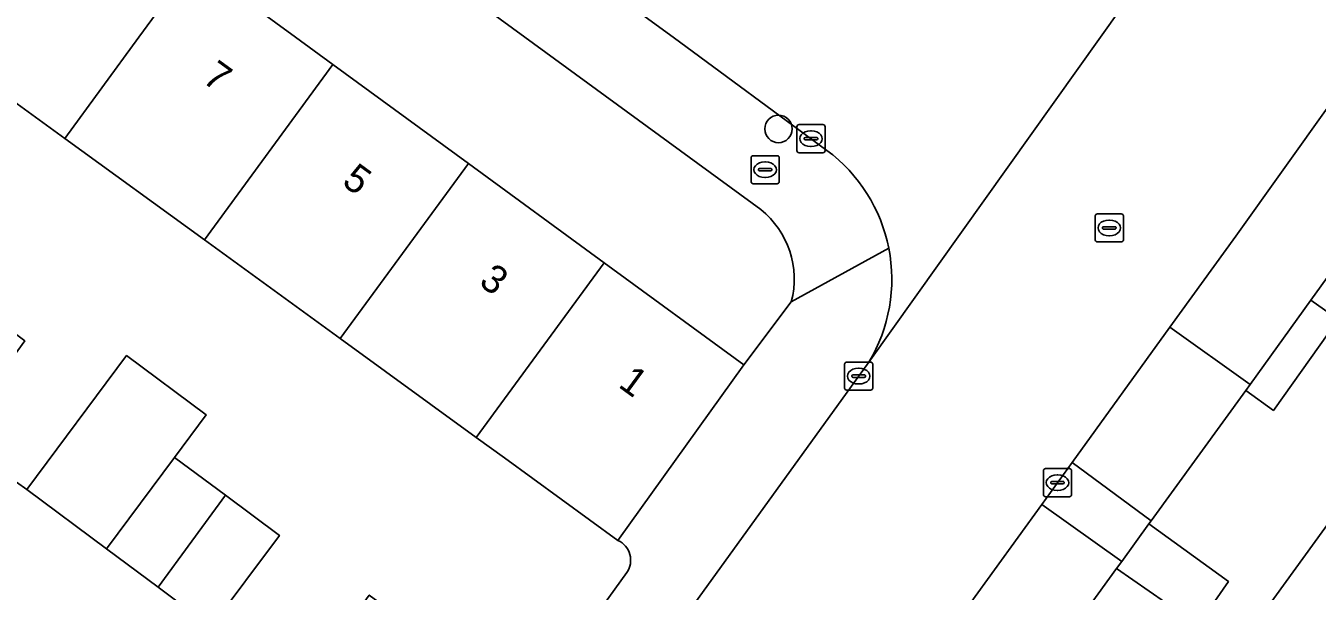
# Model space of a CAD drawing. Extents: x 159674 to 160531, y 382172 to 382904.
# Drawn here: x 160175.73 to 160221.75, y 382480.25 to 382500.4 of the extents above; entities that cross this region are included whole.
import ezdxf

# ---------------------------------------------------------------- set-up
doc = ezdxf.new("R2010")
doc.units = 0
for name, color, linetype in [('IMGEO_Boom', 7, 'Continuous'), ('IMGEO_Brandkraan', 7, 'Continuous'), ('IMGEO_Erf', 7, 'Continuous'), ('IMGEO_Groenvoorziening', 7, 'Continuous'), ('IMGEO_Kolk', 7, 'Continuous'), ('IMGEO_Pand', 7, 'Continuous'), ('IMGEO_Pand_nummerreeks', 7, 'Continuous'), ('IMGEO_Rijbaan_lokaal_gesloten', 7, 'Continuous'), ('IMGEO_Rijbaan_lokaal_open', 7, 'Continuous'), ('IMGEO_Rioolput', 7, 'Continuous'), ('IMGEO_Voetpad_open', 7, 'Continuous')]:
    doc.layers.add(name, color=color, linetype=linetype)

msp = doc.modelspace()

# ---------------------------------------------------------------- linework, layer by layer
at = {"layer": 'IMGEO_Boom'}
msp.add_circle((160202.556, 382496.725), 0.489, dxfattribs=at)
at = {"layer": 'IMGEO_Brandkraan'}
for p, q in [((160201.579, 382494.846), (160201.579, 382495.698)), ((160201.654, 382495.772), (160202.506, 382495.772)), ((160202.58, 382495.698), (160202.58, 382494.846)), ((160201.838, 382495.266), (160201.838, 382495.278)), ((160201.881, 382495.315), (160202.279, 382495.315)), ((160202.067, 382495.552), (160202.092, 382495.552)), ((160202.322, 382495.278), (160202.322, 382495.266)), ((160202.506, 382494.772), (160201.654, 382494.772)), ((160202.276, 382495.229), (160201.878, 382495.229)), ((160202.09, 382494.992), (160202.065, 382494.992))]:
    msp.add_line(p, q, dxfattribs=at)
for points in [[(160201.579, 382494.846), (160201.579, 382495.698)], [(160201.654, 382495.772), (160202.506, 382495.772)], [(160202.58, 382495.698), (160202.58, 382494.846)], [(160202.506, 382494.772), (160201.654, 382494.772)]]:
    msp.add_lwpolyline(points, dxfattribs=at)
for centre, radius, start, end in [((160201.656, 382495.696), 0.0765, 91.552, 178.448), ((160201.656, 382495.696), 0.0765, 91.552, 178.448), ((160202.504, 382495.696), 0.0765, 1.552, 88.448), ((160202.504, 382495.696), 0.0765, 1.552, 88.448), ((160201.878, 382495.275), 0.0403, 85.8775, 175.7526), ((160201.875, 382495.265), 0.0366, 178.938, 274.7102), ((160202.279, 382495.272), 0.043, 264.8664, 352.4533), ((160202.283, 382495.277), 0.0386, 1.7309, 96.639), ((160201.656, 382494.848), 0.0765, 181.552, 268.448), ((160201.656, 382494.848), 0.0765, 181.552, 268.448), ((160202.504, 382494.848), 0.0765, 271.552, 358.448), ((160202.504, 382494.848), 0.0765, 271.552, 358.448)]:
    msp.add_arc(centre, radius, start, end, dxfattribs=at)
for centre, major_axis, ratio, start_param, end_param in [((160202.066, 382495.272), (-0.387, 0.002), 0.722429, 4.712389, 7.853982), ((160202.091, 382495.272), (-0.39, 0.002), 0.717154, 1.570796, 4.712389)]:
    msp.add_ellipse(centre, major_axis=major_axis, ratio=ratio, start_param=start_param, end_param=end_param, dxfattribs=at)
at = {"layer": 'IMGEO_Erf'}
for points in [[(160193.511, 382500), (160179.581, 382510.186), (160176.698, 382506.323), (160181.704, 382502.662), (160185.344, 382500), (160186.672, 382499.029), (160191.502, 382495.496), (160196.341, 382491.958), (160201.314, 382488.321), (160203.011, 382490.565)], [(160182.094, 382492.77), (160177.116, 382496.389), (160172.149, 382500), (160165.851, 382491.086), (160168.791, 382488.896), (160171.386, 382492.38), (160173.197, 382491.031), (160175.695, 382489.17), (160173.177, 382485.697), (160175.768, 382483.874), (160179.323, 382488.647), (160182.164, 382486.531), (160181.035, 382485.016), (160182.848, 382483.665), (160184.767, 382482.236), (160182.34, 382478.979), (160182.963, 382478.515), (160185.543, 382476.768), (160187.968, 382480.105), (160192.854, 382476.554), (160193.609, 382475.995), (160197.153, 382480.914)], [(160201.923, 382493.849), (160193.511, 382500)], [(160196.833, 382482.055), (160192.788, 382484.995), (160191.782, 382485.726), (160186.934, 382489.251), (160182.094, 382492.77)]]:
    msp.add_lwpolyline(points, dxfattribs=at)
for centre, radius, start, end in [((160199.942, 382491.37), 3.173, 345.2972, 51.3632), ((160196.512, 382481.349), 0.775, 325.8286, 65.5044)]:
    msp.add_arc(centre, radius, start, end, dxfattribs=at)
at = {"layer": 'IMGEO_Groenvoorziening'}
for points in [[(160222.498, 382489.927), (160221.527, 382490.625), (160219.36, 382487.613), (160219.207, 382487.402), (160220.191, 382486.689)], [(160215.757, 382482.642), (160214.787, 382481.302), (160214.604, 382481.05), (160217.516, 382479.035), (160218.591, 382480.589)]]:
    msp.add_lwpolyline(points, close=True, dxfattribs=at)
at = {"layer": 'IMGEO_Kolk'}
for p, q in [((160203.212, 382495.953), (160203.212, 382496.805)), ((160203.287, 382496.879), (160204.139, 382496.879)), ((160203.7, 382496.659), (160203.725, 382496.659)), ((160204.213, 382496.805), (160204.213, 382495.953)), ((160203.471, 382496.373), (160203.471, 382496.385)), ((160203.909, 382496.336), (160203.511, 382496.336)), ((160203.514, 382496.422), (160203.912, 382496.422)), ((160203.955, 382496.385), (160203.955, 382496.373)), ((160204.139, 382495.879), (160203.287, 382495.879)), ((160203.723, 382496.099), (160203.698, 382496.099)), ((160204.912, 382487.487), (160204.912, 382488.339)), ((160204.987, 382488.413), (160205.839, 382488.413)), ((160205.913, 382488.339), (160205.913, 382487.487)), ((160205.171, 382487.907), (160205.171, 382487.919)), ((160205.609, 382487.87), (160205.211, 382487.87)), ((160205.214, 382487.956), (160205.612, 382487.956)), ((160205.4, 382488.193), (160205.425, 382488.193)), ((160205.655, 382487.919), (160205.655, 382487.907)), ((160205.839, 382487.413), (160204.987, 382487.413)), ((160205.423, 382487.633), (160205.398, 382487.633)), ((160211.996, 382483.689), (160211.996, 382484.541)), ((160212.071, 382484.615), (160212.923, 382484.615)), ((160212.484, 382484.395), (160212.509, 382484.395)), ((160212.997, 382484.541), (160212.997, 382483.689)), ((160212.255, 382484.109), (160212.255, 382484.121)), ((160212.693, 382484.072), (160212.295, 382484.072)), ((160212.298, 382484.158), (160212.696, 382484.158)), ((160212.507, 382483.835), (160212.482, 382483.835)), ((160212.739, 382484.121), (160212.739, 382484.109)), ((160212.923, 382483.615), (160212.071, 382483.615))]:
    msp.add_line(p, q, dxfattribs=at)
for points in [[(160203.212, 382495.953), (160203.212, 382496.805)], [(160203.287, 382496.879), (160204.139, 382496.879)], [(160204.213, 382496.805), (160204.213, 382495.953)], [(160204.139, 382495.879), (160203.287, 382495.879)], [(160204.912, 382487.487), (160204.912, 382488.339)], [(160204.987, 382488.413), (160205.839, 382488.413)], [(160205.913, 382488.339), (160205.913, 382487.487)], [(160205.839, 382487.413), (160204.987, 382487.413)], [(160211.996, 382483.689), (160211.996, 382484.541)], [(160212.071, 382484.615), (160212.923, 382484.615)], [(160212.997, 382484.541), (160212.997, 382483.689)], [(160212.923, 382483.615), (160212.071, 382483.615)]]:
    msp.add_lwpolyline(points, dxfattribs=at)
for centre, radius, start, end in [((160203.289, 382496.803), 0.0765, 91.552, 178.448), ((160203.289, 382496.803), 0.0765, 91.552, 178.448), ((160204.137, 382496.803), 0.0765, 1.552, 88.448), ((160204.137, 382496.803), 0.0765, 1.552, 88.448), ((160203.511, 382496.382), 0.0403, 85.8775, 175.7526), ((160203.508, 382496.372), 0.0366, 178.938, 274.7102), ((160203.912, 382496.379), 0.043, 264.8664, 352.4533), ((160203.916, 382496.384), 0.0386, 1.7309, 96.639), ((160203.289, 382495.955), 0.0765, 181.552, 268.448), ((160203.289, 382495.955), 0.0765, 181.552, 268.448), ((160204.137, 382495.955), 0.0765, 271.552, 358.448), ((160204.137, 382495.955), 0.0765, 271.552, 358.448), ((160204.989, 382488.337), 0.0765, 91.552, 178.448), ((160204.989, 382488.337), 0.0765, 91.552, 178.448), ((160205.837, 382488.337), 0.0765, 1.552, 88.448), ((160205.837, 382488.337), 0.0765, 1.552, 88.448), ((160205.211, 382487.916), 0.0403, 85.8775, 175.7526), ((160205.208, 382487.906), 0.0366, 178.938, 274.7102), ((160205.612, 382487.913), 0.043, 264.8664, 352.4533), ((160205.616, 382487.918), 0.0386, 1.7309, 96.639), ((160204.989, 382487.489), 0.0765, 181.552, 268.448), ((160204.989, 382487.489), 0.0765, 181.552, 268.448), ((160205.837, 382487.489), 0.0765, 271.552, 358.448), ((160205.837, 382487.489), 0.0765, 271.552, 358.448), ((160212.073, 382484.539), 0.0765, 91.552, 178.448), ((160212.073, 382484.539), 0.0765, 91.552, 178.448), ((160212.921, 382484.539), 0.0765, 1.552, 88.448), ((160212.921, 382484.539), 0.0765, 1.552, 88.448), ((160212.295, 382484.118), 0.0403, 85.8775, 175.7526), ((160212.292, 382484.108), 0.0366, 178.938, 274.7102), ((160212.696, 382484.115), 0.043, 264.8664, 352.4533), ((160212.7, 382484.12), 0.0386, 1.7309, 96.639), ((160212.073, 382483.691), 0.0765, 181.552, 268.448), ((160212.073, 382483.691), 0.0765, 181.552, 268.448), ((160212.921, 382483.691), 0.0765, 271.552, 358.448), ((160212.921, 382483.691), 0.0765, 271.552, 358.448)]:
    msp.add_arc(centre, radius, start, end, dxfattribs=at)
for centre, major_axis, ratio, start_param, end_param in [((160203.699, 382496.379), (-0.387, 0.002), 0.722429, 4.712389, 7.853982), ((160203.724, 382496.379), (-0.39, 0.002), 0.717154, 1.570796, 4.712389), ((160205.399, 382487.913), (-0.387, 0.002), 0.722429, 4.712389, 7.853982), ((160205.424, 382487.913), (-0.39, 0.002), 0.717154, 1.570796, 4.712389), ((160212.483, 382484.115), (-0.387, 0.002), 0.722429, 4.712389, 7.853982), ((160212.508, 382484.115), (-0.39, 0.002), 0.717154, 1.570796, 4.712389)]:
    msp.add_ellipse(centre, major_axis=major_axis, ratio=ratio, start_param=start_param, end_param=end_param, dxfattribs=at)
at = {"layer": 'IMGEO_Pand'}
for points in [[(160177.116, 382496.389), (160179.757, 382500), (160181.704, 382502.662), (160176.698, 382506.323), (160173.759, 382502.279), (160172.149, 382500)], [(160186.672, 382499.029), (160185.344, 382500), (160181.704, 382502.662), (160179.757, 382500), (160177.116, 382496.389), (160182.094, 382492.77)], [(160186.934, 382489.251), (160191.502, 382495.496), (160186.672, 382499.029), (160182.094, 382492.77)], [(160186.934, 382489.251), (160191.782, 382485.726), (160196.341, 382491.958), (160191.502, 382495.496)], [(160238.256, 382487.19), (160229.852, 382493.28), (160224.718, 382486.203), (160223.406, 382484.395), (160219.517, 382479.034), (160227.923, 382472.943)], [(160191.782, 382485.726), (160192.788, 382484.995), (160196.833, 382482.055), (160201.314, 382488.321), (160196.341, 382491.958)], [(160175.768, 382483.874), (160178.609, 382481.758), (160181.035, 382485.016), (160182.164, 382486.531), (160179.323, 382488.647)], [(160182.848, 382483.665), (160181.035, 382485.016), (160178.609, 382481.758), (160180.45, 382480.387)], [(160182.848, 382483.665), (160180.45, 382480.387), (160182.34, 382478.979), (160184.767, 382482.236)]]:
    msp.add_lwpolyline(points, close=True, dxfattribs=at)
at = {"layer": 'IMGEO_Rijbaan_lokaal_gesloten'}
for points in [[(160315.311, 382639.622), (160304.717, 382625.008), (160302.639, 382622.143), (160290.62, 382605.563), (160279.709, 382590.612), (160279.414, 382590.208), (160269.482, 382576.534), (160263.507, 382568.309), (160253.466, 382554.485), (160253.079, 382553.951), (160242.339, 382539.119), (160232.376, 382525.365), (160226.58, 382517.362), (160218.061, 382505.6), (160216.652, 382503.655), (160216.208, 382503.063), (160216.121, 382502.946), (160214.024, 382500), (160205.773, 382488.409), (160195.682, 382474.429), (160187.988, 382463.77), (160179.328, 382451.773), (160168.227, 382436.541)], [(160176.58, 382434.549), (160182.656, 382442.82), (160193.454, 382457.632), (160193.845, 382458.168), (160195.88, 382461.012), (160200.33, 382467.23), (160207.829, 382477.658), (160208.563, 382478.674), (160211.935, 382483.338), (160213.016, 382484.835), (160216.503, 382489.659), (160218.852, 382492.909), (160223.908, 382500), (160224.532, 382500.867), (160228.891, 382506.926), (160232.328, 382511.703), (160235.142, 382515.615), (160244.516, 382528.409), (160246.675, 382531.388), (160247.218, 382532.137), (160249.155, 382534.809), (160256.944, 382545.554)]]:
    msp.add_lwpolyline(points, dxfattribs=at)
at = {"layer": 'IMGEO_Rijbaan_lokaal_open'}
for points in [[(160170.916, 382528.842), (160166.836, 382523.227), (160198.798, 382500), (160204.282, 382495.961)], [(160205.773, 382488.409), (160214.024, 382500), (160216.121, 382502.946)]]:
    msp.add_lwpolyline(points, dxfattribs=at)
for centre, radius, start, end in [((160200.865, 382491.365), 5.727, 11.1572, 53.3718), ((160200.863, 382491.362), 5.73, 328.9754, 11.1776)]:
    msp.add_arc(centre, radius, start, end, dxfattribs=at)
at = {"layer": 'IMGEO_Rioolput'}
for p, q in [((160213.843, 382492.771), (160213.843, 382493.623)), ((160213.918, 382493.697), (160214.77, 382493.697)), ((160214.331, 382493.477), (160214.356, 382493.477)), ((160214.844, 382493.623), (160214.844, 382492.771)), ((160214.102, 382493.191), (160214.102, 382493.203)), ((160214.54, 382493.154), (160214.142, 382493.154)), ((160214.145, 382493.24), (160214.543, 382493.24)), ((160214.586, 382493.203), (160214.586, 382493.191)), ((160214.77, 382492.697), (160213.918, 382492.697)), ((160214.354, 382492.917), (160214.329, 382492.917))]:
    msp.add_line(p, q, dxfattribs=at)
for points in [[(160213.843, 382492.771), (160213.843, 382493.623)], [(160213.918, 382493.697), (160214.77, 382493.697)], [(160214.844, 382493.623), (160214.844, 382492.771)], [(160214.77, 382492.697), (160213.918, 382492.697)]]:
    msp.add_lwpolyline(points, dxfattribs=at)
for centre, radius, start, end in [((160213.92, 382493.621), 0.0765, 91.552, 178.448), ((160213.92, 382493.621), 0.0765, 91.552, 178.448), ((160214.768, 382493.621), 0.0765, 1.552, 88.448), ((160214.768, 382493.621), 0.0765, 1.552, 88.448), ((160214.142, 382493.2), 0.0403, 85.8775, 175.7526), ((160214.139, 382493.19), 0.0366, 178.938, 274.7102), ((160214.543, 382493.197), 0.043, 264.8664, 352.4533), ((160214.547, 382493.202), 0.0386, 1.7309, 96.639), ((160213.92, 382492.773), 0.0765, 181.552, 268.448), ((160213.92, 382492.773), 0.0765, 181.552, 268.448), ((160214.768, 382492.773), 0.0765, 271.552, 358.448), ((160214.768, 382492.773), 0.0765, 271.552, 358.448)]:
    msp.add_arc(centre, radius, start, end, dxfattribs=at)
for centre, major_axis, ratio, start_param, end_param in [((160214.33, 382493.197), (-0.387, 0.002), 0.722429, 4.712389, 7.853982), ((160214.355, 382493.197), (-0.39, 0.002), 0.717154, 1.570796, 4.712389)]:
    msp.add_ellipse(centre, major_axis=major_axis, ratio=ratio, start_param=start_param, end_param=end_param, dxfattribs=at)
at = {"layer": 'IMGEO_Voetpad_open'}
for points in [[(160121.273, 382553.859), (160177.794, 382512.755), (160177.234, 382512.001), (160179.581, 382510.186), (160193.511, 382500), (160201.923, 382493.849)], [(160204.282, 382495.961), (160198.798, 382500), (160166.836, 382523.227)], [(160206.484, 382492.473), (160203.011, 382490.565), (160201.314, 382488.321), (160196.833, 382482.055)], [(160203.011, 382490.565), (160206.484, 382492.473)], [(160222.841, 382492.451), (160221.527, 382490.625), (160222.498, 382489.927), (160220.191, 382486.689), (160219.207, 382487.402), (160215.841, 382482.757), (160215.757, 382482.642), (160218.591, 382480.589), (160217.516, 382479.035), (160214.604, 382481.05), (160211.397, 382476.623)], [(160197.153, 382480.914), (160193.609, 382475.995), (160195.682, 382474.429), (160205.773, 382488.409)], [(160173.525, 382478.688), (160176.28, 382476.685), (160177.398, 382478.237), (160182.767, 382474.371), (160181.626, 382472.8), (160183.129, 382471.708), (160187.174, 382468.769), (160187.611, 382469.366), (160182.799, 382472.889), (160184.062, 382474.614), (160188.874, 382471.092), (160190.085, 382472.747), (160190.429, 382473.217), (160185.543, 382476.768), (160182.963, 382478.515), (160182.34, 382478.979), (160180.45, 382480.387), (160178.609, 382481.758), (160175.768, 382483.874), (160173.177, 382485.697)], [(160219.517, 382479.034), (160223.406, 382484.395)]]:
    msp.add_lwpolyline(points, dxfattribs=at)
for points in [[(160227.391, 382498.775), (160227.898, 382499.479), (160228.273, 382500), (160229.377, 382501.534), (160231.777, 382504.869), (160228.891, 382506.926), (160224.532, 382500.867), (160223.908, 382500), (160218.852, 382492.909), (160216.503, 382489.659), (160219.36, 382487.613), (160221.527, 382490.625), (160222.841, 382492.451)], [(160219.207, 382487.402), (160219.36, 382487.613), (160216.503, 382489.659), (160213.016, 382484.835), (160215.841, 382482.757)], [(160213.016, 382484.835), (160211.935, 382483.338), (160214.787, 382481.302), (160215.757, 382482.642), (160215.841, 382482.757)], [(160214.604, 382481.05), (160214.787, 382481.302), (160211.935, 382483.338), (160208.563, 382478.674), (160211.397, 382476.623)]]:
    msp.add_lwpolyline(points, close=True, dxfattribs=at)
for centre, radius, start, end in [((160200.865, 382491.365), 5.727, 11.1572, 53.3718), ((160199.942, 382491.37), 3.173, 345.2972, 51.3632), ((160200.863, 382491.362), 5.73, 328.9754, 11.1776), ((160196.512, 382481.349), 0.775, 325.8286, 65.5044)]:
    msp.add_arc(centre, radius, start, end, dxfattribs=at)

# ---------------------------------------------------------------- texts
at = {"layer": 'IMGEO_Pand_nummerreeks'}
for s, rotation, p in [('7', 323.9243, (160181.98, 382498.426)), ('5', 323.8217, (160186.955, 382494.758)), ('3', 323.8217, (160191.835, 382491.189)), ('1', 323.8217, (160196.808, 382487.553))]:
    msp.add_text(s, height=1, rotation=rotation, dxfattribs=at).set_placement(p)

doc.saveas('drawing.dxf')
